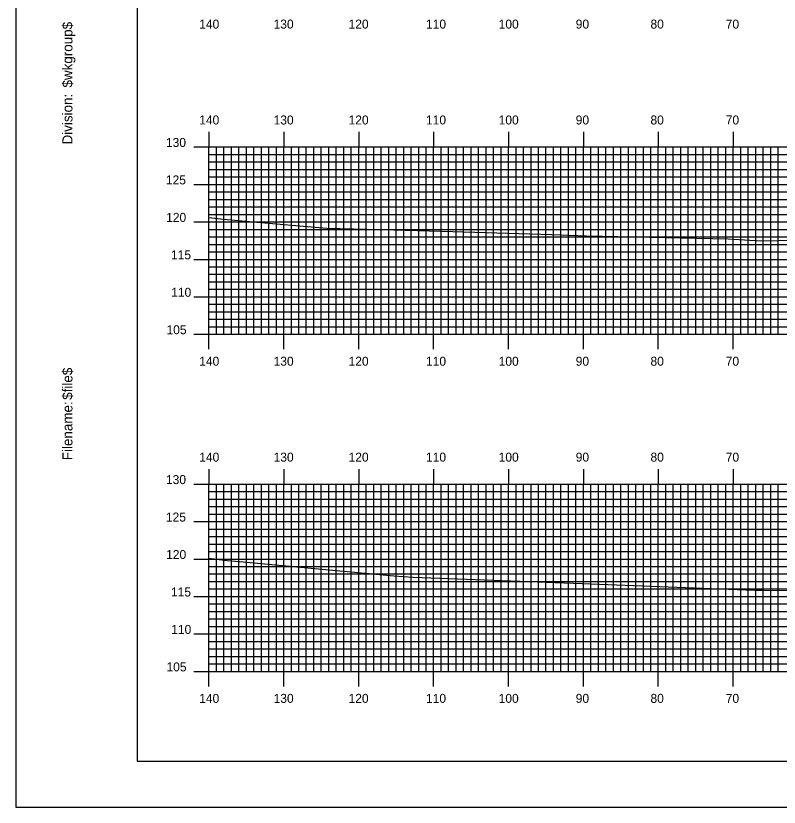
# Model space of a CAD drawing. Extents: x 1780286 to 1780629, y 442591 to 442811.
# Drawn here: x 1780286.1 to 1780388, y 442590.5 to 442696.2 of the extents above; entities that cross this region are included whole.
import ezdxf

# ---------------------------------------------------------------- set-up
doc = ezdxf.new("R2010")
doc.units = 0
for name, color, linetype in [('BORDER', 7, 'Continuous'), ('H_V ANNOTATION', 7, 'Continuous'), ('MAJOR', 7, 'Continuous'), ('MINOR', 7, 'Continuous'), ('PLOT BOUNDARY', 7, 'Continuous'), ('S_Roadway_Centerline', 7, 'Continuous')]:
    doc.layers.add(name, color=color, linetype=linetype)

msp = doc.modelspace()

# ---------------------------------------------------------------- linework, layer by layer
at = {"layer": 'BORDER'}
msp.add_lwpolyline([(1780302.27, 442596.67), (1780622.27, 442596.67), (1780622.27, 442806.67), (1780302.27, 442806.67)], close=True, dxfattribs=at)
at = {"layer": 'MAJOR'}
for p, q in [((1780311.87, 442680.67), (1780311.87, 442678.67)), ((1780321.87, 442680.67), (1780321.87, 442678.67)), ((1780331.87, 442680.67), (1780331.87, 442678.67)), ((1780341.87, 442680.67), (1780341.87, 442678.67)), ((1780351.87, 442680.67), (1780351.87, 442678.67)), ((1780361.87, 442680.67), (1780361.87, 442678.67)), ((1780371.87, 442680.67), (1780371.87, 442678.67)), ((1780381.87, 442680.67), (1780381.87, 442678.67)), ((1780309.86, 442678.67), (1780311.87, 442678.67)), ((1780311.87, 442678.67), (1780591.87, 442678.67)), ((1780311.87, 442653.67), (1780311.87, 442678.67)), ((1780311.87, 442653.67), (1780311.87, 442678.67)), ((1780311.87, 442678.67), (1780591.87, 442678.67)), ((1780321.87, 442653.67), (1780321.87, 442678.67)), ((1780331.87, 442653.67), (1780331.87, 442678.67)), ((1780341.87, 442653.67), (1780341.87, 442678.67)), ((1780351.87, 442653.67), (1780351.87, 442678.67)), ((1780361.87, 442653.67), (1780361.87, 442678.67)), ((1780371.87, 442653.67), (1780371.87, 442678.67)), ((1780381.87, 442653.67), (1780381.87, 442678.67)), ((1780309.86, 442673.67), (1780311.87, 442673.67)), ((1780311.87, 442673.67), (1780591.87, 442673.67)), ((1780309.86, 442668.67), (1780311.87, 442668.67)), ((1780311.87, 442668.67), (1780591.87, 442668.67)), ((1780309.86, 442663.67), (1780311.87, 442663.67)), ((1780311.87, 442663.67), (1780591.87, 442663.67)), ((1780309.86, 442658.67), (1780311.87, 442658.67)), ((1780311.87, 442658.67), (1780591.87, 442658.67)), ((1780309.86, 442653.67), (1780311.87, 442653.67)), ((1780311.87, 442653.67), (1780591.87, 442653.67)), ((1780311.87, 442653.67), (1780591.87, 442653.67)), ((1780311.87, 442651.66), (1780311.87, 442653.67)), ((1780321.87, 442651.66), (1780321.87, 442653.67)), ((1780331.87, 442651.66), (1780331.87, 442653.67)), ((1780341.87, 442651.66), (1780341.87, 442653.67)), ((1780351.87, 442651.66), (1780351.87, 442653.67)), ((1780361.87, 442651.66), (1780361.87, 442653.67)), ((1780371.87, 442651.66), (1780371.87, 442653.67)), ((1780381.87, 442651.66), (1780381.87, 442653.67)), ((1780311.87, 442635.67), (1780311.87, 442633.67)), ((1780321.87, 442635.67), (1780321.87, 442633.67)), ((1780331.87, 442635.67), (1780331.87, 442633.67)), ((1780341.87, 442635.67), (1780341.87, 442633.67)), ((1780351.87, 442635.67), (1780351.87, 442633.67)), ((1780361.87, 442635.67), (1780361.87, 442633.67)), ((1780371.87, 442635.67), (1780371.87, 442633.67)), ((1780381.87, 442635.67), (1780381.87, 442633.67)), ((1780309.86, 442633.67), (1780311.87, 442633.67)), ((1780311.87, 442633.67), (1780591.87, 442633.67)), ((1780311.87, 442608.67), (1780311.87, 442633.67)), ((1780311.87, 442608.67), (1780311.87, 442633.67)), ((1780311.87, 442633.67), (1780591.87, 442633.67)), ((1780321.87, 442608.67), (1780321.87, 442633.67)), ((1780331.87, 442608.67), (1780331.87, 442633.67)), ((1780341.87, 442608.67), (1780341.87, 442633.67)), ((1780351.87, 442608.67), (1780351.87, 442633.67)), ((1780361.87, 442608.67), (1780361.87, 442633.67)), ((1780371.87, 442608.67), (1780371.87, 442633.67)), ((1780381.87, 442608.67), (1780381.87, 442633.67)), ((1780309.86, 442628.67), (1780311.87, 442628.67)), ((1780311.87, 442628.67), (1780591.87, 442628.67)), ((1780309.86, 442623.67), (1780311.87, 442623.67)), ((1780311.87, 442623.67), (1780591.87, 442623.67)), ((1780309.86, 442618.67), (1780311.87, 442618.67)), ((1780311.87, 442618.67), (1780591.87, 442618.67)), ((1780309.86, 442613.67), (1780311.87, 442613.67)), ((1780311.87, 442613.67), (1780591.87, 442613.67)), ((1780309.86, 442608.67), (1780311.87, 442608.67)), ((1780311.87, 442608.67), (1780591.87, 442608.67)), ((1780311.87, 442608.67), (1780591.87, 442608.67)), ((1780311.87, 442606.66), (1780311.87, 442608.67)), ((1780321.87, 442606.66), (1780321.87, 442608.67)), ((1780331.87, 442606.66), (1780331.87, 442608.67)), ((1780341.87, 442606.66), (1780341.87, 442608.67)), ((1780351.87, 442606.66), (1780351.87, 442608.67)), ((1780361.87, 442606.66), (1780361.87, 442608.67)), ((1780371.87, 442606.66), (1780371.87, 442608.67)), ((1780381.87, 442606.66), (1780381.87, 442608.67))]:
    msp.add_line(p, q, dxfattribs=at)
at = {"layer": 'MINOR'}
for p, q in [((1780312.87, 442653.67), (1780312.87, 442678.67)), ((1780313.87, 442653.67), (1780313.87, 442678.67)), ((1780314.87, 442653.67), (1780314.87, 442678.67)), ((1780315.87, 442653.67), (1780315.87, 442678.67)), ((1780316.87, 442653.67), (1780316.87, 442678.67)), ((1780317.87, 442653.67), (1780317.87, 442678.67)), ((1780318.87, 442653.67), (1780318.87, 442678.67)), ((1780319.87, 442653.67), (1780319.87, 442678.67)), ((1780320.87, 442653.67), (1780320.87, 442678.67)), ((1780322.87, 442653.67), (1780322.87, 442678.67)), ((1780323.87, 442653.67), (1780323.87, 442678.67)), ((1780324.87, 442653.67), (1780324.87, 442678.67)), ((1780325.87, 442653.67), (1780325.87, 442678.67)), ((1780326.87, 442653.67), (1780326.87, 442678.67)), ((1780327.87, 442653.67), (1780327.87, 442678.67)), ((1780328.87, 442653.67), (1780328.87, 442678.67)), ((1780329.87, 442653.67), (1780329.87, 442678.67)), ((1780330.87, 442653.67), (1780330.87, 442678.67)), ((1780332.87, 442653.67), (1780332.87, 442678.67)), ((1780333.87, 442653.67), (1780333.87, 442678.67)), ((1780334.87, 442653.67), (1780334.87, 442678.67)), ((1780335.87, 442653.67), (1780335.87, 442678.67)), ((1780336.87, 442653.67), (1780336.87, 442678.67)), ((1780337.87, 442653.67), (1780337.87, 442678.67)), ((1780338.87, 442653.67), (1780338.87, 442678.67)), ((1780339.87, 442653.67), (1780339.87, 442678.67)), ((1780340.87, 442653.67), (1780340.87, 442678.67)), ((1780342.87, 442653.67), (1780342.87, 442678.67)), ((1780343.87, 442653.67), (1780343.87, 442678.67)), ((1780344.87, 442653.67), (1780344.87, 442678.67)), ((1780345.87, 442653.67), (1780345.87, 442678.67)), ((1780346.87, 442653.67), (1780346.87, 442678.67)), ((1780347.87, 442653.67), (1780347.87, 442678.67)), ((1780348.87, 442653.67), (1780348.87, 442678.67)), ((1780349.87, 442653.67), (1780349.87, 442678.67)), ((1780350.87, 442653.67), (1780350.87, 442678.67)), ((1780352.87, 442653.67), (1780352.87, 442678.67)), ((1780353.87, 442653.67), (1780353.87, 442678.67)), ((1780354.87, 442653.67), (1780354.87, 442678.67)), ((1780355.87, 442653.67), (1780355.87, 442678.67)), ((1780356.87, 442653.67), (1780356.87, 442678.67)), ((1780357.87, 442653.67), (1780357.87, 442678.67)), ((1780358.87, 442653.67), (1780358.87, 442678.67)), ((1780359.87, 442653.67), (1780359.87, 442678.67)), ((1780360.87, 442653.67), (1780360.87, 442678.67)), ((1780362.87, 442653.67), (1780362.87, 442678.67)), ((1780363.87, 442653.67), (1780363.87, 442678.67)), ((1780364.87, 442653.67), (1780364.87, 442678.67)), ((1780365.87, 442653.67), (1780365.87, 442678.67)), ((1780366.87, 442653.67), (1780366.87, 442678.67)), ((1780367.87, 442653.67), (1780367.87, 442678.67)), ((1780368.87, 442653.67), (1780368.87, 442678.67)), ((1780369.87, 442653.67), (1780369.87, 442678.67)), ((1780370.87, 442653.67), (1780370.87, 442678.67)), ((1780372.87, 442653.67), (1780372.87, 442678.67)), ((1780373.87, 442653.67), (1780373.87, 442678.67)), ((1780374.87, 442653.67), (1780374.87, 442678.67)), ((1780375.87, 442653.67), (1780375.87, 442678.67)), ((1780376.87, 442653.67), (1780376.87, 442678.67)), ((1780377.87, 442653.67), (1780377.87, 442678.67)), ((1780378.87, 442653.67), (1780378.87, 442678.67)), ((1780379.87, 442653.67), (1780379.87, 442678.67)), ((1780380.87, 442653.67), (1780380.87, 442678.67)), ((1780382.87, 442653.67), (1780382.87, 442678.67)), ((1780383.87, 442653.67), (1780383.87, 442678.67)), ((1780384.87, 442653.67), (1780384.87, 442678.67)), ((1780385.87, 442653.67), (1780385.87, 442678.67)), ((1780386.87, 442653.67), (1780386.87, 442678.67)), ((1780387.87, 442653.67), (1780387.87, 442678.67)), ((1780311.87, 442677.67), (1780591.87, 442677.67)), ((1780311.87, 442677.67), (1780313.87, 442677.67)), ((1780311.87, 442676.67), (1780591.87, 442676.67)), ((1780311.87, 442676.67), (1780313.87, 442676.67)), ((1780311.87, 442675.67), (1780591.87, 442675.67)), ((1780311.87, 442675.67), (1780313.87, 442675.67)), ((1780311.87, 442674.67), (1780591.87, 442674.67)), ((1780311.87, 442674.67), (1780313.87, 442674.67)), ((1780311.87, 442672.67), (1780591.87, 442672.67)), ((1780311.87, 442672.67), (1780313.87, 442672.67)), ((1780311.87, 442671.67), (1780591.87, 442671.67)), ((1780311.87, 442671.67), (1780313.87, 442671.67)), ((1780311.87, 442670.67), (1780591.87, 442670.67)), ((1780311.87, 442670.67), (1780313.87, 442670.67)), ((1780311.87, 442669.67), (1780591.87, 442669.67)), ((1780311.87, 442669.67), (1780313.87, 442669.67)), ((1780311.87, 442667.67), (1780591.87, 442667.67)), ((1780311.87, 442667.67), (1780313.87, 442667.67)), ((1780311.87, 442666.67), (1780591.87, 442666.67)), ((1780311.87, 442666.67), (1780313.87, 442666.67)), ((1780311.87, 442665.67), (1780591.87, 442665.67)), ((1780311.87, 442665.67), (1780313.87, 442665.67)), ((1780311.87, 442664.67), (1780591.87, 442664.67)), ((1780311.87, 442664.67), (1780313.87, 442664.67)), ((1780311.87, 442662.67), (1780591.87, 442662.67)), ((1780311.87, 442662.67), (1780313.87, 442662.67)), ((1780311.87, 442661.67), (1780591.87, 442661.67)), ((1780311.87, 442661.67), (1780313.87, 442661.67)), ((1780311.87, 442660.67), (1780591.87, 442660.67)), ((1780311.87, 442660.67), (1780313.87, 442660.67)), ((1780311.87, 442659.67), (1780591.87, 442659.67)), ((1780311.87, 442659.67), (1780313.87, 442659.67)), ((1780311.87, 442657.67), (1780591.87, 442657.67)), ((1780311.87, 442657.67), (1780313.87, 442657.67)), ((1780311.87, 442656.67), (1780591.87, 442656.67)), ((1780311.87, 442656.67), (1780313.87, 442656.67)), ((1780311.87, 442655.67), (1780591.87, 442655.67)), ((1780311.87, 442655.67), (1780313.87, 442655.67)), ((1780311.87, 442654.67), (1780591.87, 442654.67)), ((1780311.87, 442654.67), (1780313.87, 442654.67)), ((1780312.87, 442608.67), (1780312.87, 442633.67)), ((1780313.87, 442608.67), (1780313.87, 442633.67)), ((1780314.87, 442608.67), (1780314.87, 442633.67)), ((1780315.87, 442608.67), (1780315.87, 442633.67)), ((1780316.87, 442608.67), (1780316.87, 442633.67)), ((1780317.87, 442608.67), (1780317.87, 442633.67)), ((1780318.87, 442608.67), (1780318.87, 442633.67)), ((1780319.87, 442608.67), (1780319.87, 442633.67)), ((1780320.87, 442608.67), (1780320.87, 442633.67)), ((1780322.87, 442608.67), (1780322.87, 442633.67)), ((1780323.87, 442608.67), (1780323.87, 442633.67)), ((1780324.87, 442608.67), (1780324.87, 442633.67)), ((1780325.87, 442608.67), (1780325.87, 442633.67)), ((1780326.87, 442608.67), (1780326.87, 442633.67)), ((1780327.87, 442608.67), (1780327.87, 442633.67)), ((1780328.87, 442608.67), (1780328.87, 442633.67)), ((1780329.87, 442608.67), (1780329.87, 442633.67)), ((1780330.87, 442608.67), (1780330.87, 442633.67)), ((1780332.87, 442608.67), (1780332.87, 442633.67)), ((1780333.87, 442608.67), (1780333.87, 442633.67)), ((1780334.87, 442608.67), (1780334.87, 442633.67)), ((1780335.87, 442608.67), (1780335.87, 442633.67)), ((1780336.87, 442608.67), (1780336.87, 442633.67)), ((1780337.87, 442608.67), (1780337.87, 442633.67)), ((1780338.87, 442608.67), (1780338.87, 442633.67)), ((1780339.87, 442608.67), (1780339.87, 442633.67)), ((1780340.87, 442608.67), (1780340.87, 442633.67)), ((1780342.87, 442608.67), (1780342.87, 442633.67)), ((1780343.87, 442608.67), (1780343.87, 442633.67)), ((1780344.87, 442608.67), (1780344.87, 442633.67)), ((1780345.87, 442608.67), (1780345.87, 442633.67)), ((1780346.87, 442608.67), (1780346.87, 442633.67)), ((1780347.87, 442608.67), (1780347.87, 442633.67)), ((1780348.87, 442608.67), (1780348.87, 442633.67)), ((1780349.87, 442608.67), (1780349.87, 442633.67)), ((1780350.87, 442608.67), (1780350.87, 442633.67)), ((1780352.87, 442608.67), (1780352.87, 442633.67)), ((1780353.87, 442608.67), (1780353.87, 442633.67)), ((1780354.87, 442608.67), (1780354.87, 442633.67)), ((1780355.87, 442608.67), (1780355.87, 442633.67)), ((1780356.87, 442608.67), (1780356.87, 442633.67)), ((1780357.87, 442608.67), (1780357.87, 442633.67)), ((1780358.87, 442608.67), (1780358.87, 442633.67)), ((1780359.87, 442608.67), (1780359.87, 442633.67)), ((1780360.87, 442608.67), (1780360.87, 442633.67)), ((1780362.87, 442608.67), (1780362.87, 442633.67)), ((1780363.87, 442608.67), (1780363.87, 442633.67)), ((1780364.87, 442608.67), (1780364.87, 442633.67)), ((1780365.87, 442608.67), (1780365.87, 442633.67)), ((1780366.87, 442608.67), (1780366.87, 442633.67)), ((1780367.87, 442608.67), (1780367.87, 442633.67)), ((1780368.87, 442608.67), (1780368.87, 442633.67)), ((1780369.87, 442608.67), (1780369.87, 442633.67)), ((1780370.87, 442608.67), (1780370.87, 442633.67)), ((1780372.87, 442608.67), (1780372.87, 442633.67)), ((1780373.87, 442608.67), (1780373.87, 442633.67)), ((1780374.87, 442608.67), (1780374.87, 442633.67)), ((1780375.87, 442608.67), (1780375.87, 442633.67)), ((1780376.87, 442608.67), (1780376.87, 442633.67)), ((1780377.87, 442608.67), (1780377.87, 442633.67)), ((1780378.87, 442608.67), (1780378.87, 442633.67)), ((1780379.87, 442608.67), (1780379.87, 442633.67)), ((1780380.87, 442608.67), (1780380.87, 442633.67)), ((1780382.87, 442608.67), (1780382.87, 442633.67)), ((1780383.87, 442608.67), (1780383.87, 442633.67)), ((1780384.87, 442608.67), (1780384.87, 442633.67)), ((1780385.87, 442608.67), (1780385.87, 442633.67)), ((1780386.87, 442608.67), (1780386.87, 442633.67)), ((1780387.87, 442608.67), (1780387.87, 442633.67)), ((1780311.87, 442632.67), (1780591.87, 442632.67)), ((1780311.87, 442632.67), (1780313.87, 442632.67)), ((1780311.87, 442631.67), (1780591.87, 442631.67)), ((1780311.87, 442631.67), (1780313.87, 442631.67)), ((1780311.87, 442630.67), (1780591.87, 442630.67)), ((1780311.87, 442630.67), (1780313.87, 442630.67)), ((1780311.87, 442629.67), (1780591.87, 442629.67)), ((1780311.87, 442629.67), (1780313.87, 442629.67)), ((1780311.87, 442627.67), (1780591.87, 442627.67)), ((1780311.87, 442627.67), (1780313.87, 442627.67)), ((1780311.87, 442626.67), (1780591.87, 442626.67)), ((1780311.87, 442626.67), (1780313.87, 442626.67)), ((1780311.87, 442625.67), (1780591.87, 442625.67)), ((1780311.87, 442625.67), (1780313.87, 442625.67)), ((1780311.87, 442624.67), (1780591.87, 442624.67)), ((1780311.87, 442624.67), (1780313.87, 442624.67)), ((1780311.87, 442622.67), (1780591.87, 442622.67)), ((1780311.87, 442622.67), (1780313.87, 442622.67)), ((1780311.87, 442621.67), (1780591.87, 442621.67)), ((1780311.87, 442621.67), (1780313.87, 442621.67)), ((1780311.87, 442620.67), (1780591.87, 442620.67)), ((1780311.87, 442620.67), (1780313.87, 442620.67)), ((1780311.87, 442619.67), (1780591.87, 442619.67)), ((1780311.87, 442619.67), (1780313.87, 442619.67)), ((1780311.87, 442617.67), (1780591.87, 442617.67)), ((1780311.87, 442617.67), (1780313.87, 442617.67)), ((1780311.87, 442616.67), (1780591.87, 442616.67)), ((1780311.87, 442616.67), (1780313.87, 442616.67)), ((1780311.87, 442615.67), (1780591.87, 442615.67)), ((1780311.87, 442615.67), (1780313.87, 442615.67)), ((1780311.87, 442614.67), (1780591.87, 442614.67)), ((1780311.87, 442614.67), (1780313.87, 442614.67)), ((1780311.87, 442612.67), (1780591.87, 442612.67)), ((1780311.87, 442612.67), (1780313.87, 442612.67)), ((1780311.87, 442611.67), (1780591.87, 442611.67)), ((1780311.87, 442611.67), (1780313.87, 442611.67)), ((1780311.87, 442610.67), (1780591.87, 442610.67)), ((1780311.87, 442610.67), (1780313.87, 442610.67)), ((1780311.87, 442609.67), (1780591.87, 442609.67)), ((1780311.87, 442609.67), (1780313.87, 442609.67))]:
    msp.add_line(p, q, dxfattribs=at)
at = {"layer": 'PLOT BOUNDARY'}
msp.add_lwpolyline([(1780286.08, 442590.55), (1780626.08, 442590.55), (1780626.08, 442810.55), (1780286.08, 442810.55)], close=True, dxfattribs=at)
at = {"layer": 'S_Roadway_Centerline'}
for points in [[(1780311.87, 442669.26), (1780313.82, 442669.05), (1780317.25, 442668.73), (1780327.63, 442667.81), (1780336.57, 442667.6), (1780344.45, 442667.39), (1780357.65, 442666.97), (1780362.28, 442666.8), (1780381.18, 442666.41), (1780385.56, 442666.15), (1780390.26, 442666.22), (1780405.31, 442666), (1780413.62, 442665.77), (1780426.7, 442665.56), (1780439.31, 442664.98), (1780444.55, 442664.51), (1780449.19, 442664.46), (1780462.56, 442664.28), (1780467.58, 442664.17), (1780471.44, 442664.14), (1780486.05, 442664.03), (1780489.63, 442663.98), (1780509.62, 442663.05)], [(1780311.87, 442623.77), (1780314.3, 442623.48), (1780315.95, 442623.33), (1780324.07, 442622.56), (1780336.55, 442621.44), (1780339.13, 442621.25), (1780359.28, 442620.47), (1780360.56, 442620.43), (1780384.73, 442619.52), (1780385.81, 442619.49), (1780386.91, 442619.48), (1780395.43, 442619.57)]]:
    msp.add_lwpolyline(points, dxfattribs=at)

# ---------------------------------------------------------------- texts
at = {"layer": 'BORDER'}
for s, p in [('$wkgroup$', (1780293.64, 442686.6)), ('Division:', (1780293.64, 442679)), ('$file$', (1780293.64, 442644.92)), ('Filename:', (1780293.64, 442636.86))]:
    msp.add_text(s, height=1.339, rotation=90, dxfattribs=at).set_placement(p)
at = {"layer": 'H_V ANNOTATION'}
for s, p in [('140', (1780310.57, 442694.47)), ('130', (1780320.5, 442694.47)), ('120', (1780330.51, 442694.47)), ('110', (1780340.85, 442694.47)), ('100', (1780350.55, 442694.47)), ('90', (1780360.84, 442694.47)), ('80', (1780370.82, 442694.47)), ('70', (1780380.87, 442694.47)), ('140', (1780310.57, 442681.67)), ('130', (1780320.5, 442681.67)), ('120', (1780330.51, 442681.67)), ('110', (1780340.85, 442681.67)), ('100', (1780350.55, 442681.67)), ('90', (1780360.84, 442681.67)), ('80', (1780370.82, 442681.67)), ('70', (1780380.87, 442681.67)), ('130', (1780306.13, 442678.67)), ('125', (1780306.12, 442673.67)), ('120', (1780306.15, 442668.67)), ('115', (1780306.8, 442663.67)), ('110', (1780306.83, 442658.67)), ('105', (1780306.2, 442653.67)), ('140', (1780310.57, 442649.47)), ('130', (1780320.5, 442649.47)), ('120', (1780330.51, 442649.47)), ('110', (1780340.85, 442649.47)), ('100', (1780350.55, 442649.47)), ('90', (1780360.84, 442649.47)), ('80', (1780370.82, 442649.47)), ('70', (1780380.87, 442649.47)), ('140', (1780310.57, 442636.67)), ('130', (1780320.5, 442636.67)), ('120', (1780330.51, 442636.67)), ('110', (1780340.85, 442636.67)), ('100', (1780350.55, 442636.67)), ('90', (1780360.84, 442636.67)), ('80', (1780370.82, 442636.67)), ('70', (1780380.87, 442636.67)), ('130', (1780306.13, 442633.67)), ('125', (1780306.12, 442628.67)), ('120', (1780306.15, 442623.67)), ('115', (1780306.8, 442618.67)), ('110', (1780306.83, 442613.67)), ('105', (1780306.2, 442608.67)), ('140', (1780310.57, 442604.47)), ('130', (1780320.5, 442604.47)), ('120', (1780330.51, 442604.47)), ('110', (1780340.85, 442604.47)), ('100', (1780350.55, 442604.47)), ('90', (1780360.84, 442604.47)), ('80', (1780370.82, 442604.47)), ('70', (1780380.87, 442604.47))]:
    msp.add_text(s, height=1.2, dxfattribs=at).set_placement(p)
at = {"layer": 'MAJOR'}
for p in [(1780311.86, 442653.67), (1780311.86, 442608.67)]:
    msp.add_text('-', height=0.012, dxfattribs=at).set_placement(p)

doc.saveas('drawing.dxf')
